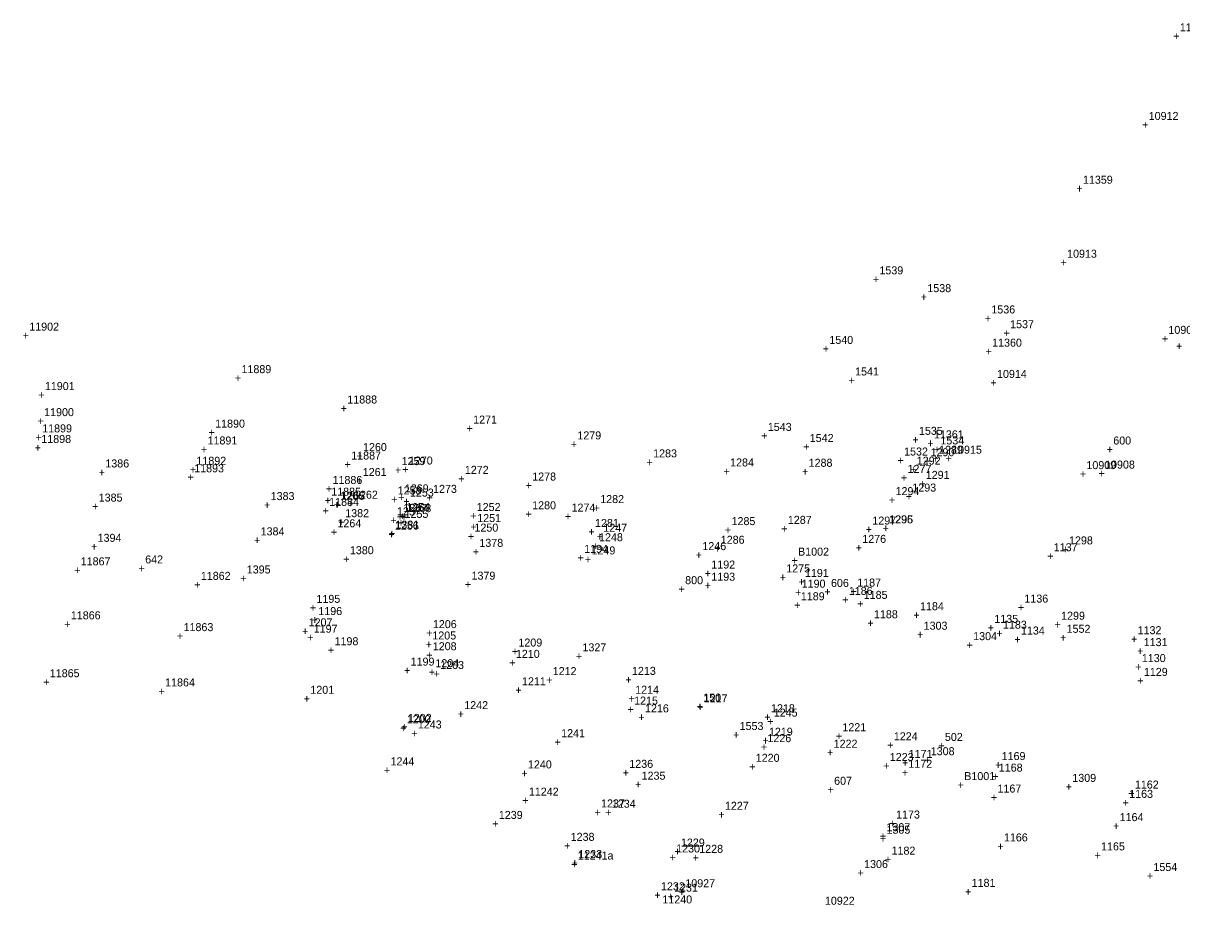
# Model space of a CAD drawing. Extents: x 1160051 to 1162814, y 614604 to 619560.
# Drawn here: x 1160933.4 to 1161295.2, y 617239.1 to 617514.7 of the extents above; entities that cross this region are included whole.
import ezdxf

# ---------------------------------------------------------------- set-up
doc = ezdxf.new("R2010")
doc.units = 0
for name, color, linetype in [('S_Control_Temp_Traverse', 7, 'Continuous'), ('S_Control_Traverse_Point', 7, 'Continuous'), ('S_Drainage_Culvert_Top', 7, 'Continuous'), ('S_Drainage_Invert', 7, 'Continuous'), ('S_Fencing_Page', 7, 'Continuous'), ('S_Ground_Elevation', 7, 'Continuous'), ('S_Ground_SpotElevation', 7, 'Continuous'), ('S_Guardrail_Beam', 7, 'Continuous'), ('S_Property_IronPipeFound', 7, 'Continuous'), ('S_Property_StoneWall', 7, 'Continuous'), ('S_Roadway_Centerline', 7, 'Continuous'), ('S_Roadway_Edge_Pavement', 7, 'Continuous'), ('S_Roadway_Edge_Shoulder', 7, 'Continuous'), ('S_Roadway_Entr_Field_Wood', 7, 'Continuous'), ('S_Roadway_Monument', 7, 'Continuous'), ('S_Trees_TreeLine', 7, 'Continuous'), ('S_Utilities_Pole_Power', 7, 'Continuous'), ('S_Utilities_UG_BoringLocation', 7, 'Continuous'), ('S_Utilities_UG_Gas_Line', 7, 'Continuous'), ('S_Utilities_UG_Sanitary_Sewer', 7, 'Continuous')]:
    doc.layers.add(name, color=color, linetype=linetype)

msp = doc.modelspace()

# ---------------------------------------------------------------- texts
at = {"layer": 'S_Control_Temp_Traverse'}
for s, p in [('600', (1161273.77, 617382.99)), ('600', (1161273.77, 617382.99)), ('600', (1161273.77, 617382.99)), ('600', (1161273.77, 617382.99)), ('+', (1161271.71, 617380.24)), ('+', (1161271.71, 617380.24)), ('+', (1161271.71, 617380.24)), ('+', (1161271.71, 617380.24)), ('642', (1160971.46, 617345.84)), ('+', (1160969.4, 617343.09)), ('800', (1161140.09, 617339.35)), ('606', (1161185.62, 617338.48)), ('606', (1161185.62, 617338.48)), ('606', (1161185.62, 617338.48)), ('+', (1161138.03, 617336.6)), ('+', (1161183.56, 617335.73)), ('+', (1161183.56, 617335.73)), ('+', (1161183.56, 617335.73)), ('150', (1161145.74, 617302.68)), ('150', (1161145.74, 617302.68)), ('+', (1161143.68, 617299.93)), ('+', (1161143.68, 617299.93)), ('+', (1161184.54, 617273.92)), ('+', (1161184.54, 617273.92)), ('607', (1161186.6, 617276.67)), ('607', (1161186.6, 617276.67))]:
    msp.add_text(s, height=2.5, dxfattribs=at).set_placement(p)
at = {"layer": 'S_Control_Traverse_Point'}
for s, p in [('502', (1161221.19, 617290.36)), ('502', (1161221.19, 617290.36)), ('502', (1161221.19, 617290.36)), ('502', (1161221.19, 617290.36)), ('+', (1161219.13, 617287.61)), ('+', (1161219.13, 617287.61)), ('+', (1161219.13, 617287.61)), ('+', (1161219.13, 617287.61))]:
    msp.add_text(s, height=2.5, dxfattribs=at).set_placement(p)
at = {"layer": 'S_Drainage_Culvert_Top'}
for s, p in [('1266', (1161032.4, 617365.73)), ('+', (1161030.34, 617362.98)), ('1267', (1161052.1, 617361.95)), ('+', (1161050.04, 617359.2))]:
    msp.add_text(s, height=2.5, dxfattribs=at).set_placement(p)
at = {"layer": 'S_Drainage_Invert'}
for s, p in [('1265', (1161032.68, 617365.75)), ('+', (1161030.62, 617363)), ('1268', (1161053.35, 617361.86)), ('+', (1161051.29, 617359.11))]:
    msp.add_text(s, height=2.5, dxfattribs=at).set_placement(p)
at = {"layer": 'S_Fencing_Page'}
for s, p in [('1292', (1161212.41, 617376.69)), ('+', (1161210.35, 617373.94)), ('1280', (1161092.31, 617362.76)), ('+', (1161090.25, 617360.01)), ('1281', (1161111.93, 617357.24)), ('+', (1161109.87, 617354.49)), ('1286', (1161151.2, 617351.98)), ('+', (1161149.13, 617349.23)), ('+', (1161061.52, 617310.1)), ('1203', (1161063.58, 617312.85)), ('1216', (1161127.54, 617299.3)), ('1200', (1161053.17, 617295.91)), ('+', (1161125.48, 617296.55)), ('+', (1161051.11, 617293.16)), ('1230', (1161137.27, 617255.51)), ('+', (1161135.21, 617252.76))]:
    msp.add_text(s, height=2.5, dxfattribs=at).set_placement(p)
at = {"layer": 'S_Ground_Elevation'}
for s, p in [('11358', (1161294.55, 617512.13)), ('+', (1161292.49, 617509.38)), ('+', (1161262.24, 617461.74)), ('11359', (1161264.3, 617464.49)), ('1539', (1161200.74, 617436.17)), ('+', (1161198.68, 617433.42)), ('1538', (1161215.71, 617430.61)), ('+', (1161213.65, 617427.87)), ('1536', (1161235.7, 617423.95)), ('11902', (1160935.26, 617418.57)), ('+', (1161233.64, 617421.2)), ('1537', (1161241.56, 617419.35)), ('+', (1160933.2, 617415.82)), ('1540', (1161185.11, 617414.44)), ('+', (1161239.5, 617416.6)), ('+', (1161183.05, 617411.69)), ('11360', (1161235.94, 617413.57)), ('+', (1161293.36, 617412.51)), ('+', (1161233.88, 617410.82)), ('11889', (1161001.54, 617405.3)), ('1541', (1161193.15, 617404.57)), ('+', (1160999.48, 617402.55)), ('+', (1161191.09, 617401.82)), ('+', (1161032.51, 617393.06)), ('11888', (1161034.58, 617395.81)), ('11900', (1160939.91, 617391.86)), ('1271', (1161073.88, 617389.53)), ('+', (1160937.85, 617389.11)), ('11899', (1160939.31, 617386.78)), ('+', (1161071.81, 617386.78)), ('1543', (1161165.89, 617387.25)), ('1535', (1161213.08, 617386.02)), ('+', (1160937.25, 617384.03)), ('11898', (1160939.03, 617383.48)), ('11891', (1160990.94, 617383.01)), ('1279', (1161106.42, 617384.6)), ('+', (1161163.83, 617384.5)), ('1542', (1161178.98, 617383.79)), ('+', (1161211.02, 617383.27)), ('+', (1161215.71, 617382.16)), ('11361', (1161217.77, 617384.91)), ('1534', (1161219.78, 617383.02)), ('+', (1160936.96, 617380.73)), ('+', (1160988.87, 617380.26)), ('+', (1161104.36, 617381.85)), ('1283', (1161130.09, 617378.97)), ('+', (1161176.92, 617381.04)), ('1532', (1161208.45, 617379.56)), ('+', (1161217.72, 617380.27)), ('1289', (1161219.37, 617380.09)), ('11892', (1160987.47, 617376.67)), ('1270', (1161053.81, 617376.74)), ('+', (1161128.03, 617376.22)), ('1284', (1161154.12, 617376.15)), ('1288', (1161178.64, 617376.04)), ('+', (1161206.39, 617376.81)), ('+', (1161217.31, 617377.34)), ('10908', (1161271.21, 617375.48)), ('+', (1160984.71, 617371.56)), ('+', (1160985.41, 617373.92)), ('11893', (1160986.77, 617374.31)), ('+', (1161051.75, 617373.99)), ('1272', (1161071.28, 617373.83)), ('1278', (1161092.33, 617371.74)), ('+', (1161152.05, 617373.4)), ('+', (1161176.58, 617373.29)), ('1291', (1161215.21, 617372.26)), ('+', (1161269.14, 617372.73)), ('+', (1161027.91, 617367.92)), ('11886', (1161029.97, 617370.67)), ('1269', (1161052.55, 617368.05)), ('+', (1161069.22, 617371.08)), ('+', (1161090.27, 617368.99)), ('1294', (1161205.78, 617367.18)), ('1293', (1161211.03, 617368.29)), ('+', (1161213.15, 617369.51)), ('+', (1161027.51, 617364.27)), ('11884', (1161028.91, 617363.81)), ('11885', (1161029.57, 617367.02)), ('+', (1161050.49, 617365.3)), ('+', (1161052.08, 617363.98)), ('1253', (1161054.14, 617366.73)), ('1282', (1161113.56, 617364.7)), ('+', (1161203.71, 617364.43)), ('+', (1161208.97, 617365.54)), ('+', (1161026.85, 617361.06)), ('1254', (1161052.97, 617362.17)), ('1252', (1161074.99, 617362.22)), ('+', (1161111.5, 617361.95)), ('+', (1161050.91, 617359.42)), ('+', (1161072.93, 617359.47)), ('1251', (1161075.15, 617358.77)), ('1285', (1161154.57, 617357.81)), ('1287', (1161172.15, 617358.2)), ('1297', (1161198.53, 617357.98)), ('1296', (1161203.76, 617358.36)), ('1295', (1161203.83, 617358.35)), ('+', (1161073.08, 617356.02)), ('1248', (1161113.19, 617352.79)), ('1247', (1161114.53, 617355.74)), ('+', (1161152.51, 617355.06)), ('+', (1161170.09, 617355.45)), ('+', (1161196.47, 617355.23)), ('+', (1161201.7, 617355.61)), ('+', (1161201.77, 617355.6)), ('+', (1161111.13, 617350.04)), ('+', (1161112.47, 617352.99)), ('1246', (1161145.45, 617350)), ('1137', (1161255.17, 617349.64)), ('+', (1161143.39, 617347.25)), ('+', (1161253.11, 617346.89)), ('+', (1160949.27, 617342.49)), ('11867', (1160951.33, 617345.24)), ('1192', (1161148.25, 617344.23)), ('11862', (1160988.84, 617340.71)), ('+', (1161146.19, 617341.48)), ('+', (1161175.42, 617338.85)), ('1190', (1161176.47, 617338.26)), ('1191', (1161177.48, 617341.6)), ('1187', (1161193.81, 617338.61)), ('+', (1160986.77, 617337.96)), ('+', (1161174.41, 617335.51)), ('1186', (1161191.19, 617336.01)), ('+', (1161191.75, 617335.86)), ('1185', (1161195.84, 617334.76)), ('+', (1161189.13, 617333.26)), ('+', (1161193.78, 617332.01)), ('1184', (1161213.42, 617331.22)), ('1136', (1161246.01, 617333.6)), ('11866', (1160948.25, 617328.36)), ('1196', (1161025.53, 617329.7)), ('+', (1161211.35, 617328.47)), ('+', (1161243.95, 617330.85)), ('+', (1160946.19, 617325.61)), ('11863', (1160983.45, 617324.68)), ('+', (1161023.47, 617326.95)), ('1197', (1161024.09, 617324.19)), ('+', (1161234.56, 617324.52)), ('1135', (1161236.62, 617327.27)), ('1183', (1161239.33, 617325.44)), ('+', (1160981.39, 617321.93)), ('+', (1161022.03, 617321.44)), ('1205', (1161061.13, 617322.07)), ('+', (1161237.27, 617322.69)), ('+', (1161242.87, 617320.87)), ('1134', (1161244.93, 617323.62)), ('+', (1161279.31, 617320.97)), ('1132', (1161281.37, 617323.72)), ('+', (1161059.07, 617319.32)), ('+', (1161281.2, 617317.24)), ('1131', (1161283.27, 617319.99)), ('1199', (1161054.36, 617313.9)), ('+', (1161085.16, 617313.57)), ('1210', (1161087.22, 617316.32)), ('1130', (1161282.69, 617315.01)), ('11865', (1160941.68, 617310.28)), ('+', (1161052.3, 617311.15)), ('+', (1161280.63, 617312.26)), ('+', (1160939.62, 617307.53)), ('11864', (1160977.69, 617307.4)), ('1211', (1161089.13, 617307.75)), ('+', (1160975.63, 617304.65)), ('1201', (1161023.04, 617305.09)), ('+', (1161087.07, 617305)), ('1214', (1161124.47, 617305.11)), ('+', (1161020.98, 617302.34)), ('1242', (1161071.1, 617300.3)), ('+', (1161122.09, 617298.98)), ('+', (1161122.41, 617302.36)), ('1215', (1161124.15, 617301.73)), ('1202', (1161053.49, 617296.31)), ('+', (1161069.04, 617297.55)), ('+', (1161051.43, 617293.56)), ('1243', (1161056.6, 617294.26)), ('1241', (1161101.37, 617291.54)), ('1219', (1161166.24, 617291.99)), ('+', (1161054.54, 617291.51)), ('+', (1161099.31, 617288.79)), ('+', (1161164.18, 617289.24)), ('1222', (1161186.45, 617288.25)), ('+', (1161184.39, 617285.5)), ('1223', (1161203.97, 617284.09)), ('1171', (1161209.88, 617285.08)), ('1244', (1161048.08, 617282.73)), ('1240', (1161090.99, 617281.78)), ('1236', (1161122.64, 617281.96)), ('+', (1161160.06, 617281.09)), ('1220', (1161162.12, 617283.84)), ('+', (1161201.91, 617281.34)), ('+', (1161207.82, 617282.33)), ('1172', (1161209.79, 617281.99)), ('1168', (1161238.02, 617280.78)), ('+', (1161046.02, 617279.98)), ('+', (1161088.93, 617279.03)), ('+', (1161120.58, 617279.21)), ('1235', (1161126.48, 617278.26)), ('+', (1161207.73, 617279.24)), ('+', (1161235.96, 617278.03)), ('11242', (1161091.28, 617273.28)), ('+', (1161124.42, 617275.51)), ('1167', (1161237.61, 617274.24)), ('+', (1161089.22, 617270.53)), ('1237', (1161113.82, 617269.58)), ('1234', (1161117.18, 617269.5)), ('+', (1161235.55, 617271.49)), ('1163', (1161278.74, 617272.58)), ('1239', (1161081.89, 617266)), ('+', (1161111.76, 617266.83)), ('+', (1161115.12, 617266.75)), ('1227', (1161152.5, 617268.85)), ('1173', (1161205.95, 617266.12)), ('+', (1161276.68, 617269.83)), ('+', (1161079.83, 617263.25)), ('+', (1161150.44, 617266.1)), ('+', (1161203.89, 617263.37)), ('1164', (1161275.75, 617265.31)), ('1238', (1161104.34, 617259.15)), ('1166', (1161239.62, 617258.97)), ('+', (1161273.69, 617262.56)), ('+', (1161102.28, 617256.4)), ('1229', (1161138.76, 617257.36)), ('1228', (1161144.48, 617255.4)), ('+', (1161237.56, 617256.22)), ('1165', (1161269.95, 617256.16)), ('11241a', (1161106.54, 617253.31)), ('1233', (1161106.72, 617253.77)), ('+', (1161136.7, 617254.61)), ('+', (1161142.42, 617252.65)), ('+', (1161202.47, 617252.08)), ('1182', (1161204.53, 617254.83)), ('+', (1161267.89, 617253.41)), ('+', (1161104.48, 617250.56)), ('+', (1161104.66, 617251.02)), ('1181', (1161229.54, 617244.77)), ('1232', (1161132.53, 617243.7)), ('1231', (1161136.62, 617243.27)), ('+', (1161227.48, 617242.02)), ('+', (1161130.47, 617240.95)), ('11240', (1161132.97, 617239.59)), ('+', (1161134.56, 617240.52))]:
    msp.add_text(s, height=2.5, dxfattribs=at).set_placement(p)
at = {"layer": 'S_Ground_SpotElevation'}
for s, p in [('1245', (1161167.75, 617297.97)), ('+', (1161165.69, 617295.22))]:
    msp.add_text(s, height=2.5, dxfattribs=at).set_placement(p)
at = {"layer": 'S_Guardrail_Beam'}
for s, p in [('10912', (1161284.83, 617484.42)), ('+', (1161282.77, 617481.67)), ('10913', (1161259.35, 617441.37)), ('+', (1161257.29, 617438.62)), ('+', (1161288.92, 617414.83)), ('10906', (1161290.98, 617417.58)), ('10914', (1161237.47, 617403.8)), ('+', (1161235.41, 617401.05)), ('10915', (1161223.44, 617380.12)), ('+', (1161221.38, 617377.37)), ('10909', (1161265.38, 617375.31)), ('+', (1161263.32, 617372.56)), ('10927', (1161140.13, 617244.65)), ('+', (1161138.07, 617241.9)), ('10922', (1161183.72, 617239.18))]:
    msp.add_text(s, height=2.5, dxfattribs=at).set_placement(p)
at = {"layer": 'S_Property_IronPipeFound'}
for s, p in [('1204', (1161062.08, 617313.41)), ('+', (1161060.02, 617310.66))]:
    msp.add_text(s, height=2.5, dxfattribs=at).set_placement(p)
at = {"layer": 'S_Property_StoneWall'}
for s, p in [('11901', (1160940.14, 617400.01)), ('+', (1160938.08, 617397.26)), ('11890', (1160993.32, 617388.27)), ('+', (1160991.25, 617385.52)), ('11887', (1161035.8, 617378.31)), ('+', (1161033.74, 617375.56))]:
    msp.add_text(s, height=2.5, dxfattribs=at).set_placement(p)
at = {"layer": 'S_Roadway_Centerline'}
for s, p in [('1385', (1160956.95, 617365.16)), ('+', (1160954.89, 617362.41)), ('1384', (1161007.52, 617354.6)), ('+', (1161005.46, 617351.85)), ('+', (1161033.33, 617345.97)), ('1380', (1161035.39, 617348.72)), ('1379', (1161073.37, 617340.77)), ('+', (1161071.31, 617338.02))]:
    msp.add_text(s, height=2.5, dxfattribs=at).set_placement(p)
at = {"layer": 'S_Roadway_Edge_Pavement'}
for s, p in [('1386', (1160959.02, 617375.83)), ('+', (1160956.96, 617373.08)), ('1383', (1161010.65, 617365.63)), ('+', (1161008.58, 617362.88)), ('1382', (1161033.93, 617360.29)), ('+', (1161031.87, 617357.54)), ('1381', (1161049.6, 617356.72)), ('+', (1161047.54, 617353.97)), ('+', (1160954.55, 617349.84)), ('1394', (1160956.61, 617352.59)), ('1378', (1161075.82, 617351.02)), ('+', (1161073.76, 617348.27)), ('1395', (1161003.19, 617342.7)), ('+', (1161001.13, 617339.95))]:
    msp.add_text(s, height=2.5, dxfattribs=at).set_placement(p)
at = {"layer": 'S_Roadway_Edge_Shoulder'}
for s, p in [('1255', (1161052.46, 617360.08)), ('+', (1161050.4, 617357.33)), ('1250', (1161074.29, 617355.78)), ('+', (1161072.23, 617353.03)), ('1194', (1161108.55, 617349.14)), ('+', (1161106.49, 617346.39)), ('+', (1161108.78, 617345.9)), ('1249', (1161110.84, 617348.65)), ('1193', (1161148.25, 617340.44)), ('+', (1161146.19, 617337.69)), ('1195', (1161024.95, 617333.52)), ('+', (1161174.14, 617331.58)), ('1189', (1161176.2, 617334.33)), ('+', (1161022.89, 617330.77)), ('1188', (1161199.04, 617328.7)), ('1206', (1161061.3, 617325.62)), ('+', (1161196.98, 617325.95)), ('1303', (1161214.55, 617325.12)), ('+', (1161059.24, 617322.87)), ('+', (1161212.49, 617322.37)), ('1304', (1161230.02, 617321.86)), ('+', (1161085.95, 617317.12)), ('1209', (1161088.01, 617319.87)), ('+', (1161227.95, 617319.11)), ('1213', (1161123.47, 617311.01)), ('1129', (1161283.32, 617310.69)), ('+', (1161121.41, 617308.26)), ('+', (1161281.26, 617307.94)), ('1218', (1161166.89, 617299.33)), ('+', (1161164.83, 617296.58)), ('1221', (1161189.18, 617293.42)), ('+', (1161187.12, 617290.67)), ('1224', (1161205.24, 617290.57)), ('+', (1161203.18, 617287.82)), ('1169', (1161238.91, 617284.39)), ('+', (1161236.85, 617281.64)), ('1162', (1161280.51, 617275.48)), ('+', (1161278.45, 617272.73))]:
    msp.add_text(s, height=2.5, dxfattribs=at).set_placement(p)
at = {"layer": 'S_Roadway_Entr_Field_Wood'}
for s, p in [('1260', (1161039.49, 617380.95)), ('+', (1161037.43, 617378.2)), ('1259', (1161051.53, 617376.56)), ('1261', (1161039.4, 617373.15)), ('+', (1161049.47, 617373.81)), ('+', (1161037.34, 617370.4)), ('1258', (1161050.32, 617367.39)), ('1262', (1161036.68, 617366.06)), ('+', (1161048.26, 617364.64)), ('+', (1161034.62, 617363.31)), ('1257', (1161050.07, 617360.86)), ('+', (1161048.01, 617358.11)), ('1256', (1161049.45, 617356.4)), ('+', (1161047.39, 617353.65))]:
    msp.add_text(s, height=2.5, dxfattribs=at).set_placement(p)
at = {"layer": 'S_Roadway_Monument'}
for s, p in [('1198', (1161030.6, 617320.28)), ('+', (1161028.54, 617317.53))]:
    msp.add_text(s, height=2.5, dxfattribs=at).set_placement(p)
at = {"layer": 'S_Trees_TreeLine'}
for s, p in [('1290', (1161216.72, 617379.33)), ('+', (1161214.66, 617376.58)), ('+', (1161207.47, 617371.39)), ('1277', (1161209.53, 617374.14)), ('1273', (1161061.36, 617367.89)), ('+', (1161059.3, 617365.14)), ('1274', (1161104.6, 617362.03)), ('+', (1161102.53, 617359.28)), ('+', (1161193.33, 617349.51)), ('1276', (1161195.39, 617352.26)), ('1298', (1161259.95, 617351.78)), ('+', (1161257.89, 617349.03)), ('1275', (1161171.65, 617343.03)), ('+', (1161169.59, 617340.28)), ('1299', (1161257.48, 617328.24)), ('1207', (1161022.51, 617326.18)), ('+', (1161255.42, 617325.49)), ('+', (1161020.44, 617323.43)), ('1208', (1161061.27, 617318.71)), ('+', (1161059.21, 617315.96)), ('1212', (1161098.72, 617310.93)), ('+', (1161096.66, 617308.18)), ('1226', (1161165.77, 617289.99)), ('+', (1161163.71, 617287.24)), ('1308', (1161216.77, 617285.91)), ('+', (1161214.7, 617283.16)), ('1309', (1161260.98, 617277.57)), ('+', (1161258.92, 617274.82)), ('+', (1161200.88, 617259.42)), ('1307', (1161202.94, 617262.17)), ('1305', (1161202.95, 617261.37)), ('+', (1161200.89, 617258.62)), ('1306', (1161195.96, 617250.65)), ('+', (1161193.89, 617247.9))]:
    msp.add_text(s, height=2.5, dxfattribs=at).set_placement(p)
at = {"layer": 'S_Utilities_Pole_Power'}
for s, p in [('1217', (1161145.88, 617302.44)), ('+', (1161143.82, 617299.69))]:
    msp.add_text(s, height=2.5, dxfattribs=at).set_placement(p)
at = {"layer": 'S_Utilities_UG_BoringLocation'}
for s, p in [('B1002', (1161175.33, 617348.27)), ('+', (1161173.27, 617345.52)), ('1552', (1161259.2, 617324.16)), ('+', (1161257.13, 617321.41)), ('1553', (1161157.08, 617293.79)), ('+', (1161155.02, 617291.04)), ('B1001', (1161227.23, 617278.13)), ('+', (1161225.17, 617275.38)), ('1554', (1161286.31, 617249.72)), ('+', (1161284.25, 617246.97))]:
    msp.add_text(s, height=2.5, dxfattribs=at).set_placement(p)
at = {"layer": 'S_Utilities_UG_Gas_Line'}
for s, p in [('1264', (1161031.5, 617357.13)), ('+', (1161029.44, 617354.38))]:
    msp.add_text(s, height=2.5, dxfattribs=at).set_placement(p)
at = {"layer": 'S_Utilities_UG_Sanitary_Sewer'}
for s, p in [('1327', (1161108.01, 617318.36)), ('+', (1161105.95, 617315.61))]:
    msp.add_text(s, height=2.5, dxfattribs=at).set_placement(p)

doc.saveas('drawing.dxf')
